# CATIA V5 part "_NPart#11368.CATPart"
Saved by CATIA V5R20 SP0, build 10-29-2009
Part number: DIN6325 Ø3X32
Revision: ANY
Definition: UNKNOWN
Nomenclature: DIN6325 Ø3X32
Source: Unknown
Bounding box of the stored display mesh (mm): x -1.5 to 1.5, y 0 to 32, z -1.5 to 1.5
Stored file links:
  C:\Users\Utente\Desktop\IO LAVORO\3D X SITO CF\CUMSA\3D files AE\AE 082430\_NPart#11368.CATPart
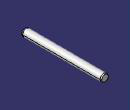
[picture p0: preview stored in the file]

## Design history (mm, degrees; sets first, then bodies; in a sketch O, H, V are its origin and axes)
Body1 "Revolución1" (main body)
  Solid1: solid without history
